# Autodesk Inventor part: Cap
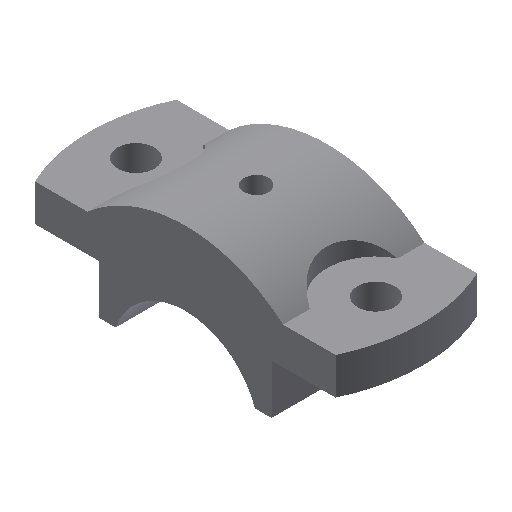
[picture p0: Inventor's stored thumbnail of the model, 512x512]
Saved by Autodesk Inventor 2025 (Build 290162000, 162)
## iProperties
Created: 2009-04
Part Number: Cap
Document SubType Name: Modeling
Designer: Sham
Density: 1 g/cm^3
Material: Generic
Appearance: Default
Author: Sham
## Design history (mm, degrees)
sketch "Sketch1"
  geometry: L1 (-48.857, 23)-(48.857, 23); L2 (48.857, -23)-(-48.857, -23); A1 r 54 centre (0, 0) between (-48.857, 23) and (-48.857, -23); A2 r 54 centre (0, 0) between (48.857, -23) and (48.857, 23); 1 further point
  constraints: 4 end point, 4 point on circle, 2 centre point, 2 coincident, 1 horizontal, 1 parallel, 1 other
  dimensions: "d3" = 54 radius of A1; "d4" = 54 radius of A2; "d5" = 46 distance between parallel lines of L2 L1; "d6" = 23 distance from line of point (0, 0) L1
extrude "Extrusion1" new body sketch "Sketch1" distance "d7" = 12; taper "d8" = 0 deg
sketch "Sketch3"
  geometry: L1 (20.906, 0)-(20.906, -16); L2 (76.906, -0.137)-(76.906, -16.137); L3 (20.906, -16)-(26.23, -16); L4 (71.532, -16.137)-(76.906, -16.137); L5 (76.906, -0.137)-(76.857, 12); L6 (97.714, 0)-(0, 0) reference; L7 (76.857, 12)-(80.606, 12); L8 (17.108, 12)-(20.906, 12); L9 (20.906, 12)-(20.906, 0); L10 (0, 12)-(97.714, 12) reference; A1 r 24 centre (48.857, -24) between (71.532, -16.137) and (26.23, -16); A2 r 48 centre (48.857, -24) between (80.606, 12) and (17.108, 12); 3 further points
  constraints: 16 end point, 4 point on circle, 3 parallel, 3 perpendicular, 2 centre point, 2 coincident, 2 vertical alignment, 1 collinear, 1 midpoint, 1 vertical, 2 other
  dimensions: "d17" = 48 diameter of A1; "d18" = 16 distance of L1.start L1.end; "d19" = 56 distance between parallel lines of L2 L1; "d21" = 8 vertical distance of A1.centre L1.end; "d22" = 48 radius of A2; "d23" = 0 distance from line of L6 L1.start; "d38" = 31.74902 distance of L7.end point (48.857, 12); "d39" = 28 distance from line of point (48.857, 12) L5
extrude "Extrusion2" join sketch "Sketch3" stored distance "d24" = 12; taper "d25" = 0 deg
sketch "Sketch4"
  geometry: 2 further points
  dimensions: "d26" = 78 distance of point (39, 0) point (-39, 0)
hole "Hole1" sketch "Sketch4" at (-39, 0), (39, 0) diameter "d28" = 12; stored, may be unused: countersink angle "d32" = 90 deg, drill point angle "d34" = 118 deg; dims "d29" = 6, "d30" = 4, "d31" = 2, "d33" = 8
sketch "Sketch5"
  geometry: L1 (-31.749, -23)-(-31.749, 23) reference; L2 (-31.749, 14.263)-(-31.749, -14.263); C1 r 6 at (-39, 0) reference; A1 r 16 centre (-39, 0) between (-31.749, -14.263) and (-31.749, 14.263)
  constraints: 2 end point, 2 point on circle, 1 centre point, 1 coincident, 1 collinear, 1 point on line
  dimensions: "d35" = 16 radius of A1
extrude "Extrusion3" cut sketch "Sketch5" distance "d36" = 12; taper "d37" = 0 deg
mirror "Mirror2"
workplane "Work Plane4"
sketch "Sketch6"
  geometry: L1 (-31.749, 0)-(31.749, 0) reference; 1 further point
  dimensions: "d40" = 23 distance from line of L1 point (0, 23)
hole "Hole2" sketch "Sketch6" at (0, 23) diameter "d41" = 6; stored, may be unused: countersink angle "d45" = 90 deg, drill point angle "d47" = 118 deg; dims "d42" = 6, "d43" = 8, "d44" = 16, "d46" = 8
body "Solid1"
